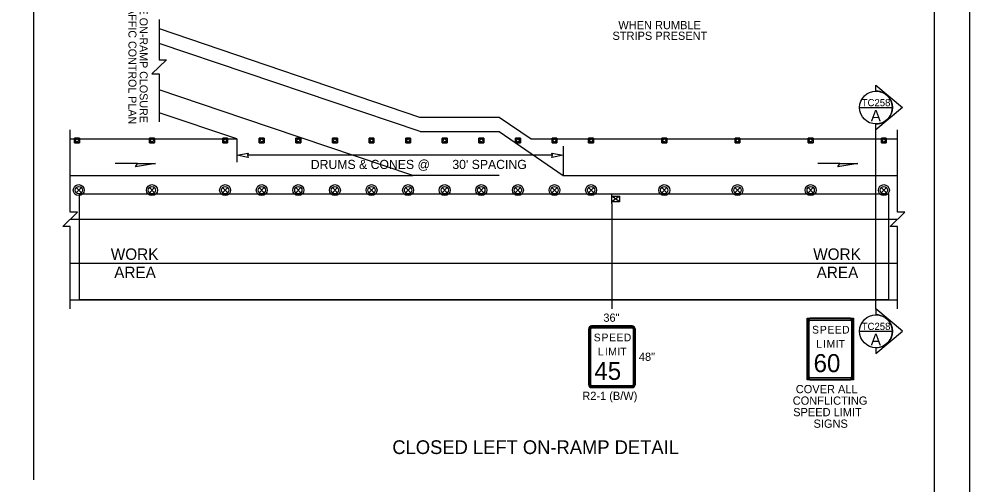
# Model space of a CAD drawing. Extents: x 99999 to 100116, y 99995 to 100013.
# Drawn here: x 100087.75 to 100096.06, y 100001.53 to 100005.61 of the extents above; entities that cross this region are included whole.
import ezdxf

# ---------------------------------------------------------------- set-up
doc = ezdxf.new("R2010")
doc.units = 0
for name, color, linetype in [('RD_MK_LineEdgeYellow', 7, 'Continuous'), ('RD_MK_LineLane', 7, 'Continuous'), ('SH_DE_DetailHeading2Text', 7, 'Continuous'), ('SH_GI_PlotLimits', 7, 'Continuous'), ('SH_GI_SectionCut', 7, 'Continuous'), ('SH_GI_SheetBorder', 7, 'Continuous'), ('TR_SN_ConstructionSigns', 7, 'Continuous'), ('TR_WZ_PortableSignMount5ftMinBlk-Wht', 7, 'Continuous'), ('TR_WZ_TrafficCone', 7, 'Continuous'), ('TR_WZ_TrafficSafetyDrum', 7, 'Continuous'), ('TR_WZ_WorkAreaLabel', 7, 'Continuous'), ('TR_WZ_WorkZoneDetails', 7, 'Continuous'), ('TR_WZ_WorkZoneTextCurrent', 7, 'Continuous')]:
    doc.layers.add(name, color=color, linetype=linetype)

msp = doc.modelspace()

# ---------------------------------------------------------------- linework, layer by layer
at = {"layer": 'RD_MK_LineEdgeYellow'}
for p, q in [((100091.2543, 100004.622), (100088.9733, 100005.3922)), ((100089.7128, 100004.7372), (100088.9733, 100004.9869)), ((100091.2543, 100004.622), (100091.9445, 100004.622)), ((100091.9445, 100004.622), (100092.5055, 100004.238)), ((100088.195, 100004.238), (100089.6524, 100004.238)), ((100092.5055, 100004.238), (100095.43, 100004.238)), ((100088.195, 100003.47), (100095.43, 100003.47))]:
    msp.add_line(p, q, dxfattribs=at)
at = {"layer": 'RD_MK_LineLane'}
for points in [[(100091.9445, 100004.238), (100091.1912, 100004.238)], [(100095.43, 100003.854), (100088.195, 100003.854)]]:
    msp.add_lwpolyline(points, dxfattribs=at)
at = {"layer": 'SH_GI_PlotLimits'}
msp.add_lwpolyline([(100079.0625, 99999.6875), (100096.0625, 99999.6875), (100096.0625, 100010.6875), (100079.0625, 100010.6875)], close=True, dxfattribs=at)
at = {"layer": 'SH_GI_SectionCut'}
for p, q in [((100095.2407, 100004.9768), (100095.2407, 100005.0277)), ((100095.2407, 100005.0277), (100095.4733, 100004.8328)), ((100095.4733, 100004.8328), (100095.2407, 100004.638)), ((100095.2407, 100004.638), (100095.2407, 100004.6888)), ((100095.2407, 100003.0699), (100095.2407, 100004.638)), ((100095.2407, 100003.07), (100095.2407, 100003.0191)), ((100095.4733, 100002.8751), (100095.2407, 100003.07)), ((100095.2407, 100002.6802), (100095.4733, 100002.8751)), ((100095.2407, 100002.7311), (100095.2407, 100002.6802))]:
    msp.add_line(p, q, dxfattribs=at)
for points in [[(100095.0967, 100004.8328), (100095.3847, 100004.8328)], [(100095.0967, 100002.8751), (100095.3847, 100002.8751)]]:
    msp.add_lwpolyline(points, dxfattribs=at)
for centre in [(100095.2407, 100004.8328), (100095.2407, 100002.8751)]:
    msp.add_circle(centre, 0.144, dxfattribs=at)
for centre in [(100095.2407, 100004.8328), (100095.2407, 100002.8751)]:
    msp.add_arc(centre, 0.144, 269.99779, 90.00221, dxfattribs=at)
at = {"layer": 'SH_GI_SheetBorder'}
msp.add_line((100095.75, 100010.375), (100095.75, 100000), dxfattribs=at)
at = {"layer": 'TR_SN_ConstructionSigns'}
for p, q in [((100094.6633, 100002.99), (100095.0177, 100002.99)), ((100095.0177, 100002.99), (100094.6633, 100002.99)), ((100095.0177, 100002.9829), (100094.6633, 100002.9829)), ((100094.6633, 100002.9731), (100095.0177, 100002.9731)), ((100092.729, 100002.4073), (100092.729, 100002.8966)), ((100092.729, 100002.8966), (100092.729, 100002.4073)), ((100092.736, 100002.8966), (100092.736, 100002.4073)), ((100092.7458, 100002.4073), (100092.7458, 100002.8966)), ((100092.7543, 100002.922), (100093.1086, 100002.922)), ((100093.1086, 100002.922), (100092.7543, 100002.922)), ((100093.1086, 100002.9149), (100092.7543, 100002.9149)), ((100092.7543, 100002.9051), (100093.1086, 100002.9051)), ((100093.1171, 100002.8966), (100093.1171, 100002.4073)), ((100093.1269, 100002.4073), (100093.1269, 100002.8966)), ((100093.134, 100002.8966), (100093.134, 100002.4073)), ((100093.134, 100002.4073), (100093.134, 100002.8966)), ((100094.638, 100002.4753), (100094.638, 100002.9646)), ((100094.638, 100002.9646), (100094.638, 100002.4753)), ((100094.6451, 100002.9646), (100094.6451, 100002.4753)), ((100094.6549, 100002.4753), (100094.6549, 100002.9646)), ((100095.0261, 100002.9646), (100095.0261, 100002.4753)), ((100095.036, 100002.4753), (100095.036, 100002.9646)), ((100095.043, 100002.9646), (100095.043, 100002.4753)), ((100095.043, 100002.4753), (100095.043, 100002.9646)), ((100093.1086, 100002.3988), (100092.7543, 100002.3988)), ((100095.0177, 100002.4668), (100094.6633, 100002.4668)), ((100094.6633, 100002.457), (100095.0177, 100002.457)), ((100095.0177, 100002.45), (100094.6633, 100002.45)), ((100094.6633, 100002.45), (100095.0177, 100002.45)), ((100092.7543, 100002.389), (100093.1086, 100002.389)), ((100093.1086, 100002.382), (100092.7543, 100002.382)), ((100092.7543, 100002.382), (100093.1086, 100002.382))]:
    msp.add_line(p, q, dxfattribs=at)
msp.add_lwpolyline([(100094.638, 100002.99), (100095.043, 100002.99), (100095.043, 100002.45), (100094.638, 100002.45)], close=True, dxfattribs=at)
for centre, radius, start, end in [((100094.6633, 100002.9646), 0.0253, 90, 180), ((100094.6633, 100002.9646), 0.0253, 90, 180), ((100094.6633, 100002.9646), 0.0183, 90, 180), ((100094.6633, 100002.9646), 0.00844, 90, 180), ((100095.0177, 100002.9646), 0.0253, 0, 90), ((100095.0177, 100002.9646), 0.0253, 360, 90), ((100095.0177, 100002.9646), 0.0183, 0, 90), ((100095.0177, 100002.9646), 0.00844, 360, 90), ((100092.7543, 100002.8966), 0.0253, 90, 180), ((100092.7543, 100002.8966), 0.0253, 90, 180), ((100092.7543, 100002.8966), 0.0183, 90, 180), ((100092.7543, 100002.8966), 0.00844, 90, 180), ((100093.1086, 100002.8966), 0.0253, 360, 90), ((100093.1086, 100002.8966), 0.0253, 360, 90), ((100093.1086, 100002.8966), 0.0183, 0, 90), ((100093.1086, 100002.8966), 0.00844, 360, 90), ((100094.6633, 100002.4753), 0.0253, 180, 270), ((100094.6633, 100002.4753), 0.0253, 180, 270), ((100094.6633, 100002.4753), 0.0183, 180, 270), ((100094.6633, 100002.4753), 0.00844, 180, 270), ((100095.0177, 100002.4753), 0.0253, 270, 0), ((100095.0177, 100002.4753), 0.0183, 270, 360), ((100095.0177, 100002.4753), 0.00844, 270, 0), ((100095.0177, 100002.4753), 0.0253, 270, 0), ((100092.7543, 100002.4073), 0.0253, 180, 270), ((100092.7543, 100002.4073), 0.0253, 180, 270), ((100092.7543, 100002.4073), 0.0183, 180, 270), ((100092.7543, 100002.4073), 0.00844, 180, 270), ((100093.1086, 100002.4073), 0.0253, 270, 360), ((100093.1086, 100002.4073), 0.0183, 270, 360), ((100093.1086, 100002.4073), 0.00844, 270, 0), ((100093.1086, 100002.4073), 0.0253, 270, 360)]:
    msp.add_arc(centre, radius, start, end, dxfattribs=at)
at = {"layer": 'TR_WZ_PortableSignMount5ftMinBlk-Wht'}
for p, q in [((100092.9315, 100003.9926), (100092.9315, 100004.0726)), ((100092.9982, 100004.0586), (100092.9315, 100004.0066)), ((100092.9982, 100004.0066), (100092.9315, 100004.0586)), ((100092.9648, 100004.0326), (100092.9648, 100004.0326)), ((100092.9649, 100004.0327), (100092.9649, 100004.0327))]:
    msp.add_line(p, q, dxfattribs=at)
msp.add_lwpolyline([(100092.9982, 100004.0586), (100092.9982, 100004.0066), (100092.9315, 100004.0066), (100092.9315, 100004.0586)], close=True, dxfattribs=at)
at = {"layer": 'TR_WZ_TrafficCone'}
for points in [[(100088.2326, 100004.5233), (100088.2753, 100004.5233), (100088.2753, 100004.566), (100088.2326, 100004.566), (100088.2326, 100004.5233)], [(100088.2326, 100004.566), (100088.2753, 100004.566), (100088.2753, 100004.5233), (100088.2326, 100004.5233), (100088.2326, 100004.566)], [(100088.8881, 100004.5233), (100088.9307, 100004.5233), (100088.9307, 100004.566), (100088.8881, 100004.566), (100088.8881, 100004.5233)], [(100088.8881, 100004.566), (100088.9307, 100004.566), (100088.9307, 100004.5233), (100088.8881, 100004.5233), (100088.8881, 100004.566)], [(100089.5281, 100004.5233), (100089.5707, 100004.5233), (100089.5707, 100004.566), (100089.5281, 100004.566), (100089.5281, 100004.5233)], [(100089.5281, 100004.566), (100089.5707, 100004.566), (100089.5707, 100004.5233), (100089.5281, 100004.5233), (100089.5281, 100004.566)], [(100089.8481, 100004.5233), (100089.8907, 100004.5233), (100089.8907, 100004.566), (100089.8481, 100004.566), (100089.8481, 100004.5233)], [(100089.8481, 100004.566), (100089.8907, 100004.566), (100089.8907, 100004.5233), (100089.8481, 100004.5233), (100089.8481, 100004.566)], [(100090.1681, 100004.5233), (100090.2107, 100004.5233), (100090.2107, 100004.566), (100090.1681, 100004.566), (100090.1681, 100004.5233)], [(100090.1681, 100004.566), (100090.2107, 100004.566), (100090.2107, 100004.5233), (100090.1681, 100004.5233), (100090.1681, 100004.566)], [(100090.4881, 100004.5233), (100090.5307, 100004.5233), (100090.5307, 100004.566), (100090.4881, 100004.566), (100090.4881, 100004.5233)], [(100090.4881, 100004.566), (100090.5307, 100004.566), (100090.5307, 100004.5233), (100090.4881, 100004.5233), (100090.4881, 100004.566)], [(100090.8081, 100004.5233), (100090.8507, 100004.5233), (100090.8507, 100004.566), (100090.8081, 100004.566), (100090.8081, 100004.5233)], [(100090.8081, 100004.566), (100090.8507, 100004.566), (100090.8507, 100004.5233), (100090.8081, 100004.5233), (100090.8081, 100004.566)], [(100091.1281, 100004.5233), (100091.1707, 100004.5233), (100091.1707, 100004.566), (100091.1281, 100004.566), (100091.1281, 100004.5233)], [(100091.1281, 100004.566), (100091.1707, 100004.566), (100091.1707, 100004.5233), (100091.1281, 100004.5233), (100091.1281, 100004.566)], [(100091.4481, 100004.5233), (100091.4907, 100004.5233), (100091.4907, 100004.566), (100091.4481, 100004.566), (100091.4481, 100004.5233)], [(100091.4481, 100004.566), (100091.4907, 100004.566), (100091.4907, 100004.5233), (100091.4481, 100004.5233), (100091.4481, 100004.566)], [(100091.7681, 100004.5233), (100091.8107, 100004.5233), (100091.8107, 100004.566), (100091.7681, 100004.566), (100091.7681, 100004.5233)], [(100091.7681, 100004.566), (100091.8107, 100004.566), (100091.8107, 100004.5233), (100091.7681, 100004.5233), (100091.7681, 100004.566)], [(100092.0881, 100004.5233), (100092.1307, 100004.5233), (100092.1307, 100004.566), (100092.0881, 100004.566), (100092.0881, 100004.5233)], [(100092.0881, 100004.566), (100092.1307, 100004.566), (100092.1307, 100004.5233), (100092.0881, 100004.5233), (100092.0881, 100004.566)], [(100092.4081, 100004.5233), (100092.4507, 100004.5233), (100092.4507, 100004.566), (100092.4081, 100004.566), (100092.4081, 100004.5233)], [(100092.4081, 100004.566), (100092.4507, 100004.566), (100092.4507, 100004.5233), (100092.4081, 100004.5233), (100092.4081, 100004.566)], [(100092.7281, 100004.5233), (100092.7707, 100004.5233), (100092.7707, 100004.566), (100092.7281, 100004.566), (100092.7281, 100004.5233)], [(100092.7281, 100004.566), (100092.7707, 100004.566), (100092.7707, 100004.5233), (100092.7281, 100004.5233), (100092.7281, 100004.566)], [(100093.3681, 100004.5233), (100093.4107, 100004.5233), (100093.4107, 100004.566), (100093.3681, 100004.566), (100093.3681, 100004.5233)], [(100093.3681, 100004.566), (100093.4107, 100004.566), (100093.4107, 100004.5233), (100093.3681, 100004.5233), (100093.3681, 100004.566)], [(100094.0081, 100004.5233), (100094.0507, 100004.5233), (100094.0507, 100004.566), (100094.0081, 100004.566), (100094.0081, 100004.5233)], [(100094.0081, 100004.566), (100094.0507, 100004.566), (100094.0507, 100004.5233), (100094.0081, 100004.5233), (100094.0081, 100004.566)], [(100094.6481, 100004.5233), (100094.6907, 100004.5233), (100094.6907, 100004.566), (100094.6481, 100004.566), (100094.6481, 100004.5233)], [(100094.6481, 100004.566), (100094.6907, 100004.566), (100094.6907, 100004.5233), (100094.6481, 100004.5233), (100094.6481, 100004.566)], [(100095.2881, 100004.5233), (100095.3307, 100004.5233), (100095.3307, 100004.566), (100095.2881, 100004.566), (100095.2881, 100004.5233)], [(100095.2881, 100004.566), (100095.3307, 100004.566), (100095.3307, 100004.5233), (100095.2881, 100004.5233), (100095.2881, 100004.566)]]:
    msp.add_lwpolyline(points, dxfattribs=at)
for centre in [(100088.2539, 100004.5446), (100088.9094, 100004.5446), (100089.5494, 100004.5446), (100089.8694, 100004.5446), (100090.1894, 100004.5446), (100090.5094, 100004.5446), (100090.8294, 100004.5446), (100091.1494, 100004.5446), (100091.4694, 100004.5446), (100091.7894, 100004.5446), (100092.1094, 100004.5446), (100092.4294, 100004.5446), (100092.7494, 100004.5446), (100093.3894, 100004.5446), (100094.0294, 100004.5446), (100094.6694, 100004.5446), (100095.3094, 100004.5446)]:
    msp.add_circle(centre, 0.0133, dxfattribs=at)
at = {"layer": 'TR_WZ_TrafficSafetyDrum'}
for p, q in [((100088.2468, 100004.1326), (100088.292, 100004.0873)), ((100088.292, 100004.1326), (100088.2468, 100004.0873)), ((100088.8868, 100004.1326), (100088.932, 100004.0873)), ((100088.932, 100004.1326), (100088.8868, 100004.0873)), ((100089.5268, 100004.1326), (100089.572, 100004.0873)), ((100089.572, 100004.1326), (100089.5268, 100004.0873)), ((100089.8468, 100004.1326), (100089.892, 100004.0873)), ((100089.892, 100004.1326), (100089.8468, 100004.0873)), ((100090.1668, 100004.1326), (100090.212, 100004.0873)), ((100090.212, 100004.1326), (100090.1668, 100004.0873)), ((100090.4868, 100004.1326), (100090.532, 100004.0873)), ((100090.532, 100004.1326), (100090.4868, 100004.0873)), ((100090.8068, 100004.1326), (100090.852, 100004.0873)), ((100090.852, 100004.1326), (100090.8068, 100004.0873)), ((100091.1268, 100004.1326), (100091.172, 100004.0873)), ((100091.172, 100004.1326), (100091.1268, 100004.0873)), ((100091.4468, 100004.1326), (100091.492, 100004.0873)), ((100091.492, 100004.1326), (100091.4468, 100004.0873)), ((100091.7668, 100004.1326), (100091.812, 100004.0873)), ((100091.812, 100004.1326), (100091.7668, 100004.0873)), ((100092.0868, 100004.1326), (100092.132, 100004.0873)), ((100092.132, 100004.1326), (100092.0868, 100004.0873)), ((100092.4068, 100004.1326), (100092.452, 100004.0873)), ((100092.452, 100004.1326), (100092.4068, 100004.0873)), ((100092.7268, 100004.1326), (100092.772, 100004.0873)), ((100092.772, 100004.1326), (100092.7268, 100004.0873)), ((100093.3668, 100004.1326), (100093.412, 100004.0873)), ((100093.412, 100004.1326), (100093.3668, 100004.0873)), ((100094.0068, 100004.1326), (100094.052, 100004.0873)), ((100094.052, 100004.1326), (100094.0068, 100004.0873)), ((100094.6468, 100004.1326), (100094.692, 100004.0873)), ((100094.692, 100004.1326), (100094.6468, 100004.0873)), ((100095.2868, 100004.1326), (100095.332, 100004.0873)), ((100095.332, 100004.1326), (100095.2868, 100004.0873))]:
    msp.add_line(p, q, dxfattribs=at)
for centre, radius in [((100088.2694, 100004.11), 0.048), ((100088.2694, 100004.11), 0.048), ((100088.2694, 100004.11), 0.032), ((100088.9094, 100004.11), 0.048), ((100088.9094, 100004.11), 0.048), ((100088.9094, 100004.11), 0.032), ((100089.5494, 100004.11), 0.048), ((100089.5494, 100004.11), 0.048), ((100089.5494, 100004.11), 0.032), ((100089.8694, 100004.11), 0.048), ((100089.8694, 100004.11), 0.048), ((100089.8694, 100004.11), 0.032), ((100090.1894, 100004.11), 0.048), ((100090.1894, 100004.11), 0.048), ((100090.1894, 100004.11), 0.032), ((100090.5094, 100004.11), 0.048), ((100090.5094, 100004.11), 0.048), ((100090.5094, 100004.11), 0.032), ((100090.8294, 100004.11), 0.048), ((100090.8294, 100004.11), 0.048), ((100090.8294, 100004.11), 0.032), ((100091.1494, 100004.11), 0.048), ((100091.1494, 100004.11), 0.048), ((100091.1494, 100004.11), 0.032), ((100091.4694, 100004.11), 0.048), ((100091.4694, 100004.11), 0.048), ((100091.4694, 100004.11), 0.032), ((100091.7894, 100004.11), 0.048), ((100091.7894, 100004.11), 0.048), ((100091.7894, 100004.11), 0.032), ((100092.1094, 100004.11), 0.048), ((100092.1094, 100004.11), 0.048), ((100092.1094, 100004.11), 0.032), ((100092.4294, 100004.11), 0.048), ((100092.4294, 100004.11), 0.048), ((100092.4294, 100004.11), 0.032), ((100092.7494, 100004.11), 0.048), ((100092.7494, 100004.11), 0.048), ((100092.7494, 100004.11), 0.032), ((100093.3894, 100004.11), 0.048), ((100093.3894, 100004.11), 0.048), ((100093.3894, 100004.11), 0.032), ((100094.0294, 100004.11), 0.048), ((100094.0294, 100004.11), 0.048), ((100094.0294, 100004.11), 0.032), ((100094.6694, 100004.11), 0.048), ((100094.6694, 100004.11), 0.048), ((100094.6694, 100004.11), 0.032), ((100095.3094, 100004.11), 0.048), ((100095.3094, 100004.11), 0.048), ((100095.3094, 100004.11), 0.032)]:
    msp.add_circle(centre, radius, dxfattribs=at)
at = {"layer": 'TR_WZ_WorkZoneDetails'}
for p, q in [((100087.875, 100008.9181), (100087.875, 100001.5759)), ((100088.9733, 100005.5235), (100091.2488, 100004.75)), ((100089.6524, 100004.558), (100088.9733, 100004.7871)), ((100091.1912, 100004.238), (100089.7128, 100004.7372)), ((100091.2488, 100004.75), (100091.9445, 100004.75)), ((100091.9445, 100004.75), (100092.225, 100004.558)), ((100088.195, 100004.558), (100089.6524, 100004.558)), ((100089.6524, 100004.558), (100089.6524, 100004.3549)), ((100092.225, 100004.558), (100095.43, 100004.558)), ((100092.5055, 100004.4949), (100092.5055, 100004.238)), ((100092.4118, 100004.4149), (100089.7461, 100004.4149)), ((100088.782, 100004.344), (100088.5891, 100004.344)), ((100094.9242, 100004.344), (100094.7313, 100004.344)), ((100089.6524, 100004.238), (100091.1912, 100004.238)), ((100092.9315, 100003.9926), (100092.9315, 100003.07)), ((100088.195, 100003.15), (100095.43, 100003.15))]:
    msp.add_line(p, q, dxfattribs=at)
for points in [[(100088.9733, 100005.6039), (100088.9733, 100005.2515), (100089.0373, 100005.2515), (100088.9092, 100005.1276), (100088.9733, 100005.1276), (100088.9733, 100004.7071)], [(100088.195, 100003.07), (100088.195, 100003.792), (100088.131, 100003.792), (100088.259, 100003.9159), (100088.195, 100003.9159), (100088.195, 100004.638)], [(100095.43, 100003.07), (100095.43, 100003.792), (100095.366, 100003.792), (100095.494, 100003.9159), (100095.43, 100003.9159), (100095.43, 100004.638)]]:
    msp.add_lwpolyline(points, dxfattribs=at)
for points in [[(100089.6524, 100004.4149), (100089.7506, 100004.4342), (100089.7461, 100004.4149), (100089.7506, 100004.3956)], [(100092.5055, 100004.4149), (100092.4073, 100004.3956), (100092.4118, 100004.4149), (100092.4073, 100004.4342)], [(100088.9392, 100004.344), (100088.7641, 100004.3132), (100088.782, 100004.344)], [(100095.0815, 100004.344), (100094.9064, 100004.3132), (100094.9242, 100004.344)], [(100088.275, 100003.15), (100088.275, 100004.078), (100095.35, 100004.078), (100095.35, 100003.15)]]:
    msp.add_lwpolyline(points, close=True, dxfattribs=at)

# ---------------------------------------------------------------- texts
at = {"layer": 'SH_DE_DetailHeading2Text'}
msp.add_text('CLOSED LEFT ON-RAMP DETAIL', height=0.12, rotation=360, dxfattribs=at).set_placement((100091.0116, 100001.8009))
at = {"layer": 'SH_GI_SectionCut'}
for p in [(100095.1158, 100004.8444), (100095.1158, 100002.8867)]:
    msp.add_text('TC258', height=0.0625, dxfattribs=at).set_placement(p)
for p in [(100095.1945, 100004.7108), (100095.1945, 100002.7531)]:
    msp.add_text('A', height=0.1, rotation=359.99005, dxfattribs=at).set_placement(p)
at = {"layer": 'TR_SN_ConstructionSigns'}
for s, height, p in [('WHEN RUMBLE', 0.072, (100092.9875, 100005.5184)), ('STRIPS PRESENT', 0.072, (100092.9365, 100005.4247)), ('36"', 0.072, (100092.8567, 100002.958)), ('S', 0.0675, (100092.7728, 100002.787)), ('P', 0.0675, (100092.841, 100002.787)), ('E', 0.0675, (100092.9072, 100002.787)), ('E', 0.0675, (100092.9713, 100002.787)), ('D', 0.0675, (100093.0354, 100002.787)), ('L', 0.0675, (100092.8079, 100002.6632)), ('I', 0.0675, (100092.87, 100002.6632)), ('M', 0.0675, (100092.8997, 100002.6632)), ('I', 0.0675, (100092.9807, 100002.6632)), ('T', 0.0675, (100093.0044, 100002.6632)), ('48"', 0.072, (100093.1672, 100002.616)), ('R2-1 (B/W)', 0.072, (100092.6727, 100002.274))]:
    msp.add_text(s, height=height, rotation=360, dxfattribs=at).set_placement(p)
for s, height, p in [('S', 0.0675, (100094.6819, 100002.855)), ('P', 0.0675, (100094.7501, 100002.855)), ('E', 0.0675, (100094.8162, 100002.855)), ('E', 0.0675, (100094.8803, 100002.855)), ('D', 0.0675, (100094.9445, 100002.855)), ('L', 0.0675, (100094.717, 100002.7312)), ('I', 0.0675, (100094.7791, 100002.7312)), ('M', 0.0675, (100094.8088, 100002.7312)), ('I', 0.0675, (100094.8898, 100002.7312)), ('T', 0.0675, (100094.9134, 100002.7312)), ('60', 0.1575, (100094.6949, 100002.5175)), ('45', 0.1575, (100092.778, 100002.4495)), ('COVER ALL', 0.072, (100094.5392, 100002.333)), ('CONFLICTING', 0.072, (100094.5128, 100002.2322)), ('SPEED LIMIT', 0.072, (100094.5168, 100002.1314)), ('SIGNS', 0.072, (100094.6947, 100002.0306))]:
    msp.add_text(s, height=height, dxfattribs=at).set_placement(p)
at = {"layer": 'TR_WZ_WorkAreaLabel'}
for s, p in [('WORK', (100088.5496, 100003.5)), ('WORK', (100094.6919, 100003.5)), ('AREA', (100088.5793, 100003.34)), ('AREA', (100094.7215, 100003.34))]:
    msp.add_text(s, height=0.1, dxfattribs=at).set_placement(p)
at = {"layer": 'TR_WZ_WorkZoneTextCurrent'}
for s, p in [('TRAFFIC CONTROL PLAN', (100088.7037, 100005.8361)), ('SEE ON-RAMP CLOSURE', (100088.8017, 100005.8322))]:
    msp.add_text(s, height=0.07, rotation=270, dxfattribs=at).set_placement(p)
for s, p in [('DRUMS & CONES @', (100090.2984, 100004.2949)), ("30' SPACING", (100091.5362, 100004.2949))]:
    msp.add_text(s, height=0.08, dxfattribs=at).set_placement(p)

doc.saveas('drawing.dxf')
